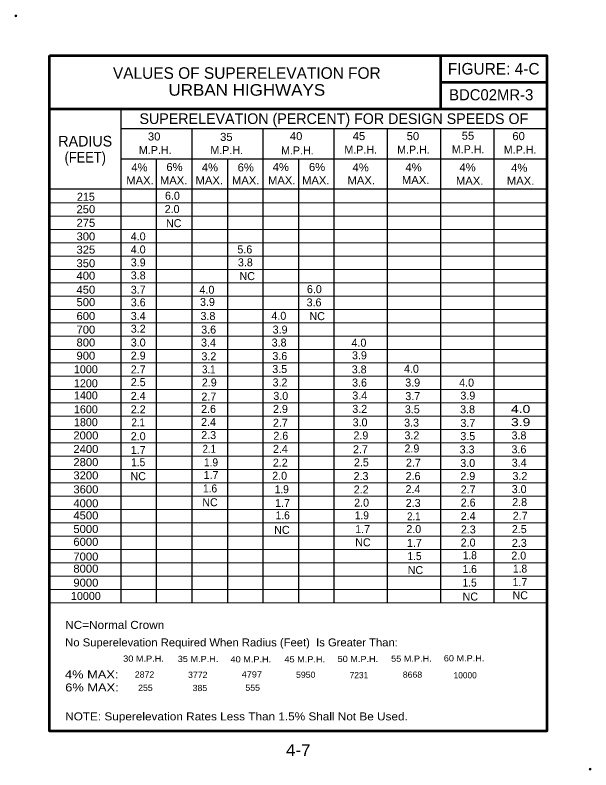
# Model space of a CAD drawing. Extents: x -3.3 to -2.46, y 2.7 to 3.81.
import ezdxf
from ezdxf.enums import TextEntityAlignment as Align

# ---------------------------------------------------------------- set-up
doc = ezdxf.new("R2010")
doc.units = 0
doc.header["$LTSCALE"] = 0.0047
doc.header["$PDMODE"] = 32
doc.header["$PDSIZE"] = 0.00235
doc.layers.add('1', color=7, linetype='Continuous', lineweight=13)

msp = doc.modelspace()

# ---------------------------------------------------------------- linework, layer by layer
at = {"layer": '1', "lineweight": 53}
for p, q in [((-2.68151, 3.746594), (-2.68151, 3.668469)), ((-2.68151, 3.707531), (-2.52526, 3.707531)), ((-3.254427, 3.668469), (-2.52526, 3.668469))]:
    msp.add_line(p, q, dxfattribs=at)
at = {"layer": '1', "lineweight": 25}
for p, q in [((-3.149979, 3.667542), (-3.149979, 2.944958)), ((-3.149979, 3.639406), (-2.52526, 3.639406)), ((-3.045812, 3.639406), (-3.045812, 2.944958)), ((-2.941646, 3.639406), (-2.941646, 2.944958)), ((-2.837479, 3.639406), (-2.837479, 2.944958)), ((-2.759354, 3.639406), (-2.759354, 2.944958)), ((-2.681229, 3.639406), (-2.681229, 2.944958)), ((-2.603104, 3.639406), (-2.603104, 2.944958)), ((-3.149979, 3.595198), (-2.52526, 3.595198)), ((-3.097896, 3.595198), (-3.097896, 2.944958)), ((-2.993729, 3.595198), (-2.993729, 2.944958)), ((-2.889562, 3.595198), (-2.889562, 2.944958)), ((-3.254146, 3.550979), (-2.52526, 3.550979))]:
    msp.add_line(p, q, dxfattribs=at)
at = {"layer": '1'}
for p, q in [((-3.254396, 3.530896), (-2.524979, 3.530896)), ((-3.254396, 3.511365), (-2.524979, 3.511365)), ((-3.254396, 3.491833), (-2.524979, 3.491833)), ((-3.254396, 3.472302), (-2.524979, 3.472302)), ((-3.254396, 3.452771), (-2.524979, 3.452771)), ((-3.254396, 3.43324), (-2.524979, 3.43324)), ((-3.254396, 3.413708), (-2.524979, 3.413708)), ((-3.254396, 3.394177), (-2.524979, 3.394177)), ((-3.254396, 3.374646), (-2.524979, 3.374646)), ((-3.254396, 3.355115), (-2.524979, 3.355115)), ((-3.254396, 3.335583), (-2.524979, 3.335583)), ((-3.254396, 3.316052), (-2.524979, 3.316052)), ((-3.254396, 3.296521), (-2.524979, 3.296521)), ((-3.254396, 3.27699), (-2.524979, 3.27699)), ((-3.254396, 3.257458), (-2.524979, 3.257458)), ((-3.254396, 3.237927), (-2.524979, 3.237927)), ((-3.254396, 3.218396), (-2.524979, 3.218396)), ((-3.254396, 3.198865), (-2.524979, 3.198865)), ((-3.254396, 3.179333), (-2.524979, 3.179333)), ((-3.254396, 3.159802), (-2.524979, 3.159802)), ((-3.254396, 3.140271), (-2.524979, 3.140271)), ((-3.254396, 3.12074), (-2.524979, 3.12074)), ((-3.254396, 3.101208), (-2.524979, 3.101208)), ((-3.254396, 3.081677), (-2.524979, 3.081677)), ((-3.254396, 3.062146), (-2.524979, 3.062146)), ((-3.254396, 3.042615), (-2.524979, 3.042615)), ((-3.254396, 3.023083), (-2.524979, 3.023083)), ((-3.254396, 3.003552), (-2.524979, 3.003552)), ((-3.254396, 2.984021), (-2.524979, 2.984021)), ((-3.254396, 2.96449), (-2.524979, 2.96449)), ((-3.254396, 2.944958), (-2.524979, 2.944958))]:
    msp.add_line(p, q, dxfattribs=at)
at = {"layer": '1', "lineweight": 53}
msp.add_lwpolyline([(-3.254427, 3.746594), (-2.52526, 3.746594), (-2.52526, 2.75701), (-3.254427, 2.75701)], close=True, dxfattribs=at)
at = {"layer": '1'}
for p in [(-3.303719, 3.804458), (-2.462052, 2.701333)]:
    msp.add_point(p, dxfattribs=at)

# ---------------------------------------------------------------- texts
for s, height, p in [('VALUES OF SUPERELEVATION FOR', 0.01693, (-2.965234, 3.712312)), ('FIGURE: 4-C', 0.01692, (-2.603391, 3.718604)), ('BDC02MR-3', 0.01628, (-2.607016, 3.680792)), ('SUPERELEVATION (PERCENT) FOR DESIGN SPEEDS OF', 0.01562, (-2.83763, 3.646125)), ('RADIUS', 0.01562, (-3.202062, 3.613167)), ('M.P.H.', 0.01172, (-2.640839, 3.603271)), ('M.P.H.', 0.01172, (-3.099453, 3.602094)), ('M.P.H.', 0.01172, (-2.994714, 3.602062)), ('M.P.H.', 0.01172, (-2.891078, 3.601573)), ('M.P.H.', 0.01172, (-2.798286, 3.602698)), ('M.P.H.', 0.01172, (-2.720964, 3.602719)), ('M.P.H.', 0.01172, (-2.56462, 3.602698)), ('215', 0.01172, (-3.201146, 3.53376)), ('6.0', 0.01172, (-3.074276, 3.535219)), ('2.0', 0.01172, (-3.074745, 3.515719)), ('NC', 0.01172, (-3.072344, 3.495021)), ('4.0', 0.01172, (-3.124422, 3.475687)), ('4.0', 0.01172, (-3.124422, 3.456573)), ('5.6', 0.01172, (-2.968141, 3.456615)), ('3.9', 0.01172, (-3.124417, 3.437552)), ('3.8', 0.01172, (-2.967375, 3.437646)), ('3.8', 0.01172, (-3.124427, 3.418562)), ('NC', 0.01172, (-2.964604, 3.417521)), ('3.7', 0.01172, (-3.124417, 3.397698)), ('4.0', 0.01172, (-3.023651, 3.397573)), ('6.0', 0.01172, (-2.866245, 3.398375)), ('3.6', 0.01172, (-3.124422, 3.379062)), ('3.9', 0.01172, (-3.022927, 3.379646)), ('3.6', 0.01172, (-2.866714, 3.379062)), ('3.4', 0.01172, (-3.124422, 3.35901)), ('3.8', 0.01172, (-3.022187, 3.359021)), ('4.0', 0.01172, (-2.918276, 3.359333)), ('NC', 0.01172, (-2.862042, 3.358854)), ('3.2', 0.01172, (-3.124422, 3.340479)), ('3.6', 0.01172, (-3.021161, 3.339187)), ('3.9', 0.01172, (-2.916458, 3.339229)), ('3.0', 0.01172, (-3.124422, 3.320271)), ('3.4', 0.01172, (-3.021422, 3.320219)), ('3.8', 0.01172, (-2.917917, 3.320229)), ('4.0', 0.01172, (-2.800891, 3.32)), ('2.9', 0.01172, (-3.124417, 3.301104)), ('3.2', 0.01172, (-3.020849, 3.300052)), ('3.6', 0.01172, (-2.91688, 3.300406)), ('3.9', 0.01172, (-2.800167, 3.301552)), ('1000', 0.01172, (-3.201141, 3.281052)), ('2.7', 0.01172, (-3.124417, 3.280885)), ('3.5', 0.01172, (-2.917031, 3.281427)), ('3.8', 0.01172, (-2.800521, 3.280896)), ('4.0', 0.01172, (-2.723901, 3.28176)), ('1200', 0.01172, (-3.201141, 3.260573)), ('2.5', 0.01172, (-3.124427, 3.262188)), ('2.9', 0.01172, (-3.020229, 3.261771)), ('3.2', 0.01172, (-2.916568, 3.261813)), ('3.6', 0.01172, (-2.800036, 3.261615)), ('3.9', 0.01172, (-2.722094, 3.261667)), ('4.0', 0.01172, (-2.643089, 3.261531)), ('1400', 0.01172, (-3.201141, 3.242833)), ('2.4', 0.01172, (-3.124422, 3.242031)), ('2.7', 0.01172, (-3.020896, 3.241)), ('3.0', 0.01172, (-2.915516, 3.242083)), ('3.4', 0.01172, (-2.799734, 3.242646)), ('3.7', 0.01172, (-2.72201, 3.24176)), ('3.9', 0.01172, (-2.641281, 3.242552)), ('1600', 0.01172, (-3.201141, 3.222385)), ('2.2', 0.01172, (-3.124422, 3.222448)), ('2.6', 0.01172, (-3.021349, 3.222979)), ('2.9', 0.01172, (-2.915948, 3.222979)), ('3.2', 0.01172, (-2.799734, 3.223021)), ('3.5', 0.01172, (-2.722656, 3.222437)), ('3.8', 0.01172, (-2.641646, 3.222448)), ('1800', 0.01172, (-3.201141, 3.203562)), ('2.4', 0.01172, (-3.021391, 3.203792)), ('2.7', 0.01172, (-2.916062, 3.20276)), ('3.0', 0.01172, (-2.799224, 3.203292)), ('3.3', 0.01172, (-2.723714, 3.202969)), ('3.7', 0.01172, (-2.641208, 3.202417)), ('2.0', 0.01172, (-3.124422, 3.182979)), ('2.3', 0.01172, (-3.02113, 3.184708)), ('2.6', 0.01172, (-2.915422, 3.183656)), ('2.9', 0.01172, (-2.798021, 3.184208)), ('3.2', 0.01172, (-2.723297, 3.184229)), ('3.5', 0.01172, (-2.641323, 3.183094)), ('3.8', 0.01172, (-2.566292, 3.184208)), ('1.7', 0.01172, (-3.124427, 3.162802)), ('2.4', 0.01172, (-2.916016, 3.164469)), ('2.7', 0.01172, (-2.798667, 3.163969)), ('2.9', 0.01172, (-2.723229, 3.165094)), ('3.3', 0.01172, (-2.642359, 3.163635)), ('3.6', 0.01172, (-2.566349, 3.163823)), ('2.2', 0.01172, (-2.91613, 3.144323)), ('2.5', 0.01172, (-2.797365, 3.14474)), ('2.7', 0.01172, (-2.721125, 3.144312)), ('3.0', 0.01172, (-2.641432, 3.14375)), ('3.4', 0.01172, (-2.566057, 3.144312)), ('NC', 0.01172, (-3.124417, 3.1245)), ('1.7', 0.01172, (-3.017708, 3.126198)), ('2.0', 0.01172, (-2.91713, 3.125073)), ('2.3', 0.01172, (-2.797828, 3.124625)), ('2.6', 0.01172, (-2.721578, 3.124656)), ('2.9', 0.01172, (-2.641323, 3.124656)), ('3.2', 0.01172, (-2.564953, 3.124687)), ('2.2', 0.01172, (-2.797651, 3.105)), ('2.4', 0.01172, (-2.721651, 3.105469)), ('2.7', 0.01172, (-2.640865, 3.10499)), ('3.0', 0.01172, (-2.566068, 3.105521)), ('NC', 0.01172, (-3.019177, 3.086271)), ('1.7', 0.01172, (-2.912875, 3.085229)), ('2.0', 0.01172, (-2.796995, 3.08575)), ('2.3', 0.01172, (-2.721391, 3.085281)), ('2.6', 0.01172, (-2.640786, 3.085875)), ('2.8', 0.01172, (-2.565365, 3.086552)), ('2.4', 0.01172, (-2.640849, 3.066135)), ('2.7', 0.01172, (-2.564615, 3.066406)), ('NC', 0.01172, (-2.913812, 3.045854)), ('1.7', 0.01172, (-2.79549, 3.04699)), ('2.0', 0.01172, (-2.720547, 3.046979)), ('2.3', 0.01172, (-2.640589, 3.0465)), ('2.5', 0.01172, (-2.565865, 3.046948)), ('NC', 0.01172, (-2.795021, 3.027646)), ('1.7', 0.01172, (-2.719604, 3.026771)), ('2.0', 0.01172, (-2.640839, 3.027312)), ('2.3', 0.01172, (-2.565797, 3.026771)), ('2.0', 0.01172, (-2.566609, 3.008177)), ('NC', 0.01172, (-2.718073, 2.986948)), ('1.7', 0.01172, (-2.564917, 2.969375)), ('10000', 0.01172, (-3.201146, 2.949073)), ('NC', 0.01172, (-2.637656, 2.948198)), ('NC', 0.01172, (-2.564448, 2.950063)), ('7231', 0.009104, (-2.800885, 2.834479)), ('10000', 0.009104, (-2.645146, 2.83424))]:
    msp.add_text(s, height=height, dxfattribs=at).set_placement(p, align=Align.CENTER)
for s, height, width, p in [('URBAN HIGHWAYS', 0.01693, 1.1, (-2.965229, 3.687573)), ('30', 0.01172, 1.05, (-3.101036, 3.62199)), ('35', 0.01172, 1.05, (-2.995198, 3.621396)), ('40', 0.01172, 1.05, (-2.893016, 3.622542)), ('45', 0.01172, 1.05, (-2.800906, 3.622542)), ('50', 0.01172, 1.05, (-2.721755, 3.622521)), ('55', 0.01172, 1.05, (-2.641083, 3.623125)), ('60', 0.01172, 1.05, (-2.56687, 3.622542)), ('(FEET)', 0.01562, 0.9, (-3.202068, 3.589729)), ('4%', 0.01172, 1.05, (-3.12262, 3.576698)), ('6%', 0.01172, 1.05, (-3.071224, 3.577271)), ('4%', 0.01172, 1.05, (-3.019318, 3.576698)), ('6%', 0.01172, 1.05, (-2.966776, 3.576687)), ('4%', 0.01172, 1.05, (-2.915422, 3.57726)), ('6%', 0.01172, 1.05, (-2.862318, 3.577271)), ('4%', 0.01172, 1.05, (-2.798339, 3.576708)), ('4%', 0.01172, 1.05, (-2.720849, 3.576698)), ('4%', 0.01172, 1.05, (-2.641661, 3.576698)), ('4%', 0.01172, 1.05, (-2.565901, 3.576115)), ('MAX.', 0.01172, 1.05, (-3.121818, 3.55774)), ('MAX.', 0.01172, 1.05, (-3.072464, 3.55774)), ('MAX.', 0.01172, 1.05, (-3.020234, 3.55774)), ('MAX.', 0.01172, 1.05, (-2.966859, 3.55774)), ('MAX.', 0.01172, 1.05, (-2.914047, 3.55774)), ('MAX.', 0.01172, 1.05, (-2.86413, 3.55774)), ('MAX.', 0.01172, 1.05, (-2.797547, 3.55774)), ('MAX.', 0.01172, 1.05, (-2.717776, 3.558312)), ('MAX.', 0.01172, 1.05, (-2.638568, 3.557167)), ('MAX.', 0.01172, 1.05, (-2.563953, 3.557167)), ('250', 0.01172, 1.05, (-3.201151, 3.515479)), ('275', 0.01172, 1.05, (-3.201146, 3.495573)), ('300', 0.01172, 1.05, (-3.201151, 3.475646)), ('325', 0.01172, 1.05, (-3.201146, 3.456302)), ('350', 0.01172, 1.05, (-3.201151, 3.436375)), ('400', 0.01172, 1.05, (-3.201151, 3.418094)), ('450', 0.01172, 1.05, (-3.201151, 3.397646)), ('500', 0.01172, 1.05, (-3.201151, 3.379375)), ('600', 0.01172, 1.05, (-3.201151, 3.359031)), ('700', 0.01172, 1.05, (-3.201151, 3.339135)), ('800', 0.01172, 1.05, (-3.201151, 3.320302)), ('900', 0.01172, 1.05, (-3.201151, 3.300937)), ('3.1', 0.01172, 0.9, (-3.021016, 3.280854)), ('4.0', 0.01172, 1.3, (-2.563854, 3.222802)), ('2.1', 0.01172, 0.9, (-3.124422, 3.203323)), ('3.9', 0.01172, 1.3, (-2.563854, 3.203615)), ('2000', 0.01172, 1.05, (-3.201146, 3.184187)), ('2400', 0.01172, 1.05, (-3.201146, 3.164271)), ('2.1', 0.01172, 0.9, (-3.020276, 3.164542)), ('2800', 0.01172, 1.05, (-3.201146, 3.145052)), ('1.5', 0.01172, 0.95, (-3.124417, 3.144885)), ('1.9', 0.01172, 0.95, (-3.017719, 3.144729)), ('3200', 0.01172, 1.05, (-3.201146, 3.125677)), ('1.6', 0.01172, 0.95, (-3.019089, 3.10651)), ('3600', 0.01172, 1.05, (-3.201146, 3.105219)), ('1.9', 0.01172, 0.95, (-2.91399, 3.105385)), ('4000', 0.01172, 1.05, (-3.201146, 3.08475)), ('4500', 0.01172, 1.05, (-3.201146, 3.067031)), ('1.6', 0.01172, 0.95, (-2.91263, 3.067177)), ('1.9', 0.01172, 0.95, (-2.796604, 3.067146)), ('2.1', 0.01172, 0.9, (-2.720526, 3.065667)), ('5000', 0.01172, 1.05, (-3.201146, 3.047125)), ('6000', 0.01172, 1.05, (-3.201146, 3.028292)), ('7000', 0.01172, 1.05, (-3.201146, 3.00676)), ('1.5', 0.01172, 0.95, (-2.719437, 3.007437)), ('1.8', 0.01172, 0.95, (-2.638417, 3.00875)), ('8000', 0.01172, 1.05, (-3.201146, 2.989031)), ('1.6', 0.01172, 0.95, (-2.638536, 2.9885)), ('1.8', 0.01172, 0.95, (-2.564719, 2.989083)), ('9000', 0.01172, 1.05, (-3.201146, 2.968542)), ('1.5', 0.01172, 0.95, (-2.638625, 2.968646)), ('30 M.P.H.', 0.009104, 1.1, (-3.116651, 2.858583)), ('35 M.P.H.', 0.009104, 1.1, (-3.036724, 2.858104)), ('40 M.P.H.', 0.009104, 1.1, (-2.959307, 2.857615)), ('45 M.P.H.', 0.009104, 1.1, (-2.880339, 2.857615)), ('50 M.P.H.', 0.009104, 1.1, (-2.802432, 2.858104)), ('55 M.P.H.', 0.009104, 1.1, (-2.723953, 2.858583)), ('60 M.P.H.', 0.009104, 1.1, (-2.646766, 2.859062)), ('2872', 0.009104, 1.05, (-3.115141, 2.835323)), ('3772', 0.009104, 1.05, (-3.03713, 2.834906)), ('4797', 0.009104, 1.1, (-2.957865, 2.835479)), ('5950', 0.009104, 1.05, (-2.878865, 2.835021)), ('8668', 0.009104, 1.05, (-2.722427, 2.835104)), ('255', 0.009104, 1.05, (-3.11388, 2.815875)), ('385', 0.009104, 1.05, (-3.033964, 2.815583)), ('555', 0.009104, 1.05, (-2.956609, 2.816031)), ('4-7', 0.01692, 1.1, (-2.889844, 2.720719))]:
    msp.add_text(s, height=height, dxfattribs=dict(at, width=width)).set_placement(p, align=Align.CENTER)
for s, width, p in [('NC=Normal Crown', 1.1, (-3.231396, 2.906656)), ('No Superelevation Required When Radius (Feet)  Is Greater Than:', 1.05, (-3.231396, 2.881031)), ('4% MAX:', 1.2, (-3.231729, 2.834094)), ('6% MAX:', 1.2, (-3.231396, 2.815083)), ('NOTE: Superelevation Rates Less Than 1.5% Shall Not Be Used.', 1.1, (-3.231396, 2.772667))]:
    msp.add_text(s, height=0.01172, dxfattribs=dict(at, width=width)).set_placement(p)

doc.saveas('drawing.dxf')
